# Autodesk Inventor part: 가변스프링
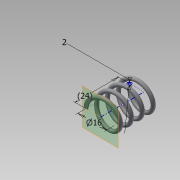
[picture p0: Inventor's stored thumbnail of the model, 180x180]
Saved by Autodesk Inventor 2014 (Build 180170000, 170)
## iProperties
Created: 2015-04
Part Number: 가변스프링
Material: Generic
Document SubType Name: Modeling
Designer: Administrator
Density: 1 g/cm^3
Appearance: Default
Mass: 0.606913 g
Surface Area: 12.5215 cm^2
Volume: 0.606913 cm^3
Author: Administrator
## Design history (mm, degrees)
sketch "스케치1"
  geometry: L1 (0, 0)-(-8, 0); L2 (-8, 0)-(-8, -11.5); L3 (-8, -11.5)-(0, -11.5); L4 (0, -11.5)-(0, 0); C1 r 1 at (-8, 0)
  constraints: 8 end point, 2 parallel, 1 centre point, 1 coincident, 1 horizontal, 1 perpendicular
  dimensions: "d0" = 2 diameter of C1; "d1" = 11.50049 distance between parallel lines of L3 L1 (derived); "d2" = 16 diameter of L2 L4
feature "코일1" pitch "d3" = 10; turns "d5" = 4; dims "d4" = 11.50049 (= d1), "d6" = 0, angle "d7" = 90 deg, angle "d8" = 90 deg, "d9" = 0, "d10" = 0
sketch "스케치2"
  geometry: L1 (7, 0)-(9, 0) reference; 1 further point
  constraints: 1 horizontal alignment
extrude "돌출1" cut sketch "스케치2" stored distance "d11" = 10; taper "d12" = 0 deg
node "작업 평면1"
sketch "스케치3"
  geometry: L1 (9, 0)-(7, 0) reference; 1 further point
  constraints: 1 horizontal alignment
extrude "돌출2" cut sketch "스케치3" stored distance "d13" = 10; taper "d14" = 0 deg
node "솔리드1"
node "절단 모서리 투영1"
node "절단 모서리 투영2"
